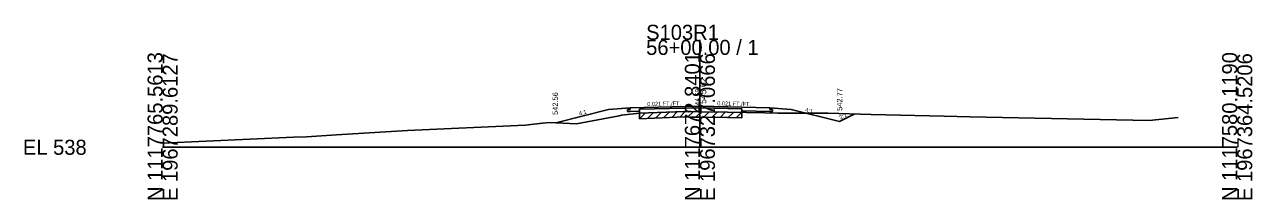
# Model space of a CAD drawing. Extents: x -26 to 203, y -10 to 12018.
# Drawn here: x -25.7 to 202.8, y 2490.3 to 2522.8 of the extents above; entities that cross this region are included whole.
import ezdxf

# ---------------------------------------------------------------- set-up
doc = ezdxf.new("R2010")
doc.units = 0
for name, color, linetype in [('Level 10', 7, 'Continuous'), ('Level 11', 7, 'Continuous'), ('Level 12', 7, 'Continuous'), ('Level 32', 7, 'Continuous'), ('Level 33', 7, 'Continuous'), ('Level 53', 7, 'Continuous'), ('Level 59', 7, 'Continuous'), ('Level 6', 7, 'Continuous'), ('Level 60', 7, 'Continuous'), ('Level 61', 7, 'Continuous'), ('Level 63', 7, 'Continuous'), ('Level 7', 7, 'Continuous')]:
    doc.layers.add(name, color=color, linetype=linetype)

msp = doc.modelspace()

# ---------------------------------------------------------------- linework, layer by layer
at = {"layer": 'Level 11'}
for p, q in [((86.5, 2507.03), (87, 2507.04)), ((86.5, 2506.67), (86.5, 2507.03)), ((87, 2507.04), (87, 2507.35)), ((113, 2507.04), (113, 2507.35)), ((113.5, 2507.03), (113, 2507.04)), ((113.5, 2506.67), (113.5, 2507.03)), ((87, 2506.68), (86.5, 2506.67)), ((113, 2506.68), (113.5, 2506.67))]:
    msp.add_line(p, q, dxfattribs=at)
at = {"layer": 'Level 12'}
for p, q in [((87, 2506.68), (88.75, 2506.71)), ((88.75, 2506.71), (88.75, 2506.31)), ((107.79, 2506.79), (107.79, 2506.46)), ((113, 2506.68), (107.79, 2506.79))]:
    msp.add_line(p, q, dxfattribs=at)
at = {"layer": 'Level 53'}
for p, q in [((88.75, 2507.07), (100, 2507.31)), ((88.75, 2506.31), (88.75, 2507.07)), ((107.79, 2507.15), (100, 2507.31)), ((107.79, 2506.46), (107.79, 2507.15))]:
    msp.add_line(p, q, dxfattribs=at)
at = {"layer": 'Level 59'}
for p, q in [((87, 2507.35), (100, 2507.62)), ((100, 2507.62), (113, 2507.35))]:
    msp.add_line(p, q, dxfattribs=at)
at = {"layer": 'Level 6'}
for p, q in [((87, 2507.35), (83, 2507.02)), ((113, 2507.35), (117, 2507.02))]:
    msp.add_line(p, q, dxfattribs=at)
at = {"layer": 'Level 60'}
for p, q in [((77.05, 2504.37), (84.99, 2505.83)), ((84.99, 2505.83), (85.42, 2505.94)), ((85.42, 2505.94), (88.75, 2506.31)), ((88.75, 2506.31), (97.16, 2506.65)), ((97.16, 2506.65), (97.5, 2506.66)), ((97.5, 2506.66), (98.31, 2506.62)), ((98.31, 2506.62), (100, 2506.59)), ((100, 2506.59), (105.14, 2506.51)), ((105.14, 2506.51), (112.08, 2506.38)), ((112.08, 2506.38), (114.53, 2506.33)), ((114.53, 2506.33), (115.01, 2506.34)), ((115.01, 2506.34), (118.64, 2506.36)), ((118.64, 2506.36), (123.86, 2506.33)), ((123.86, 2506.33), (131.86, 2506.1)), ((131.86, 2506.1), (145.49, 2505.81)), ((145.49, 2505.81), (150.26, 2505.64)), ((150.26, 2505.64), (183.6, 2505)), ((183.6, 2505), (189.01, 2505.56)), ((32.38, 2502.34), (45.61, 2503.11)), ((45.61, 2503.11), (67.45, 2504.14)), ((67.45, 2504.14), (70.69, 2504.49)), ((70.69, 2504.49), (71.92, 2504.62)), ((71.92, 2504.62), (77.05, 2504.37)), ((0, 2500.75), (24.37, 2501.85)), ((24.37, 2501.85), (26.78, 2501.95)), ((26.78, 2501.95), (32.38, 2502.34))]:
    msp.add_line(p, q, dxfattribs=at)
at = {"layer": 'Level 61'}
for p, q in [((88.75, 2505.31), (89.79, 2506.35)), ((88.75, 2505.31), (88.75, 2506.31)), ((88.75, 2505.31), (97.16, 2505.65)), ((90.25, 2505.37), (91.29, 2506.41)), ((91.75, 2505.43), (92.79, 2506.47)), ((93.25, 2505.49), (94.29, 2506.53)), ((94.75, 2505.55), (95.79, 2506.59)), ((96.25, 2505.61), (97.29, 2506.65)), ((97.16, 2505.65), (97.5, 2505.66)), ((97.5, 2505.66), (98.31, 2505.62)), ((97.75, 2505.64), (98.72, 2506.61)), ((98.31, 2505.62), (100, 2505.59)), ((99.25, 2505.61), (100.23, 2506.59)), ((100, 2505.59), (105.14, 2505.51)), ((100.75, 2505.58), (101.73, 2506.57)), ((102.25, 2505.56), (103.23, 2506.54)), ((103.75, 2505.53), (104.73, 2506.52)), ((105.14, 2505.51), (107.79, 2505.46)), ((105.25, 2505.51), (106.23, 2506.49)), ((106.75, 2505.48), (107.73, 2506.46)), ((107.79, 2506.46), (107.79, 2505.46))]:
    msp.add_line(p, q, dxfattribs=at)
at = {"layer": 'Level 63'}
for p, q in [((100, 2500), (100, 2519.97)), ((0, 2500), (100, 2500)), ((100, 2500), (200, 2500))]:
    msp.add_line(p, q, dxfattribs=at)
at = {"layer": 'Level 7'}
for p, q in [((83, 2507.02), (73.16, 2504.56)), ((117, 2507.02), (126, 2504.77)), ((126, 2504.77), (128.83, 2506.19))]:
    msp.add_line(p, q, dxfattribs=at)

# ---------------------------------------------------------------- texts
at = {"layer": 'Level 10'}
msp.add_text(' 544.59', height=0.9, rotation=90, dxfattribs=at).set_placement((100, 2506.73))
at = {"layer": 'Level 32'}
for s, rotation, p in [('0.021 FT./FT.', 1.1916, (90.21, 2507.67)), ('0.021 FT./FT.', 358.8084, (103.22, 2507.8)), ('4:1', 345.9638, (119.55, 2506.64)), ('4:1', 14.0362, (77.57, 2505.9)), ('2:1', 26.5651, (126.17, 2505.14))]:
    msp.add_text(s, height=0.75, rotation=rotation, dxfattribs=at).set_placement(p)
at = {"layer": 'Level 33'}
for s, p in [('542.56', (73.58, 2506.02)), ('542.77', (126.5, 2506.77))]:
    msp.add_text(s, height=1, rotation=90, dxfattribs=at).set_placement(p)
at = {"layer": 'Level 59'}
msp.add_text(' 545.62', height=1.2, rotation=90, dxfattribs=at).set_placement((101.2, 2507.62))
at = {"layer": 'Level 63'}
for s, p in [('S103R1', (90, 2519.97)), ('56+00.00 / 1', (90, 2517.17)), ('EL 538', (-26, 2498.6))]:
    msp.add_text(s, height=2.8, dxfattribs=at).set_placement(p)
for s, p in [('N 1117765.5613', (0, 2490)), ('E 1967289.6127', (2.8, 2490)), ('N 1117672.8401', (100, 2490)), ('E 1967327.0666', (102.8, 2490)), ('N 1117580.1190', (200, 2490)), ('E 1967364.5206', (202.8, 2490))]:
    msp.add_text(s, height=2.8, rotation=90, dxfattribs=at).set_placement(p)

doc.saveas('drawing.dxf')
